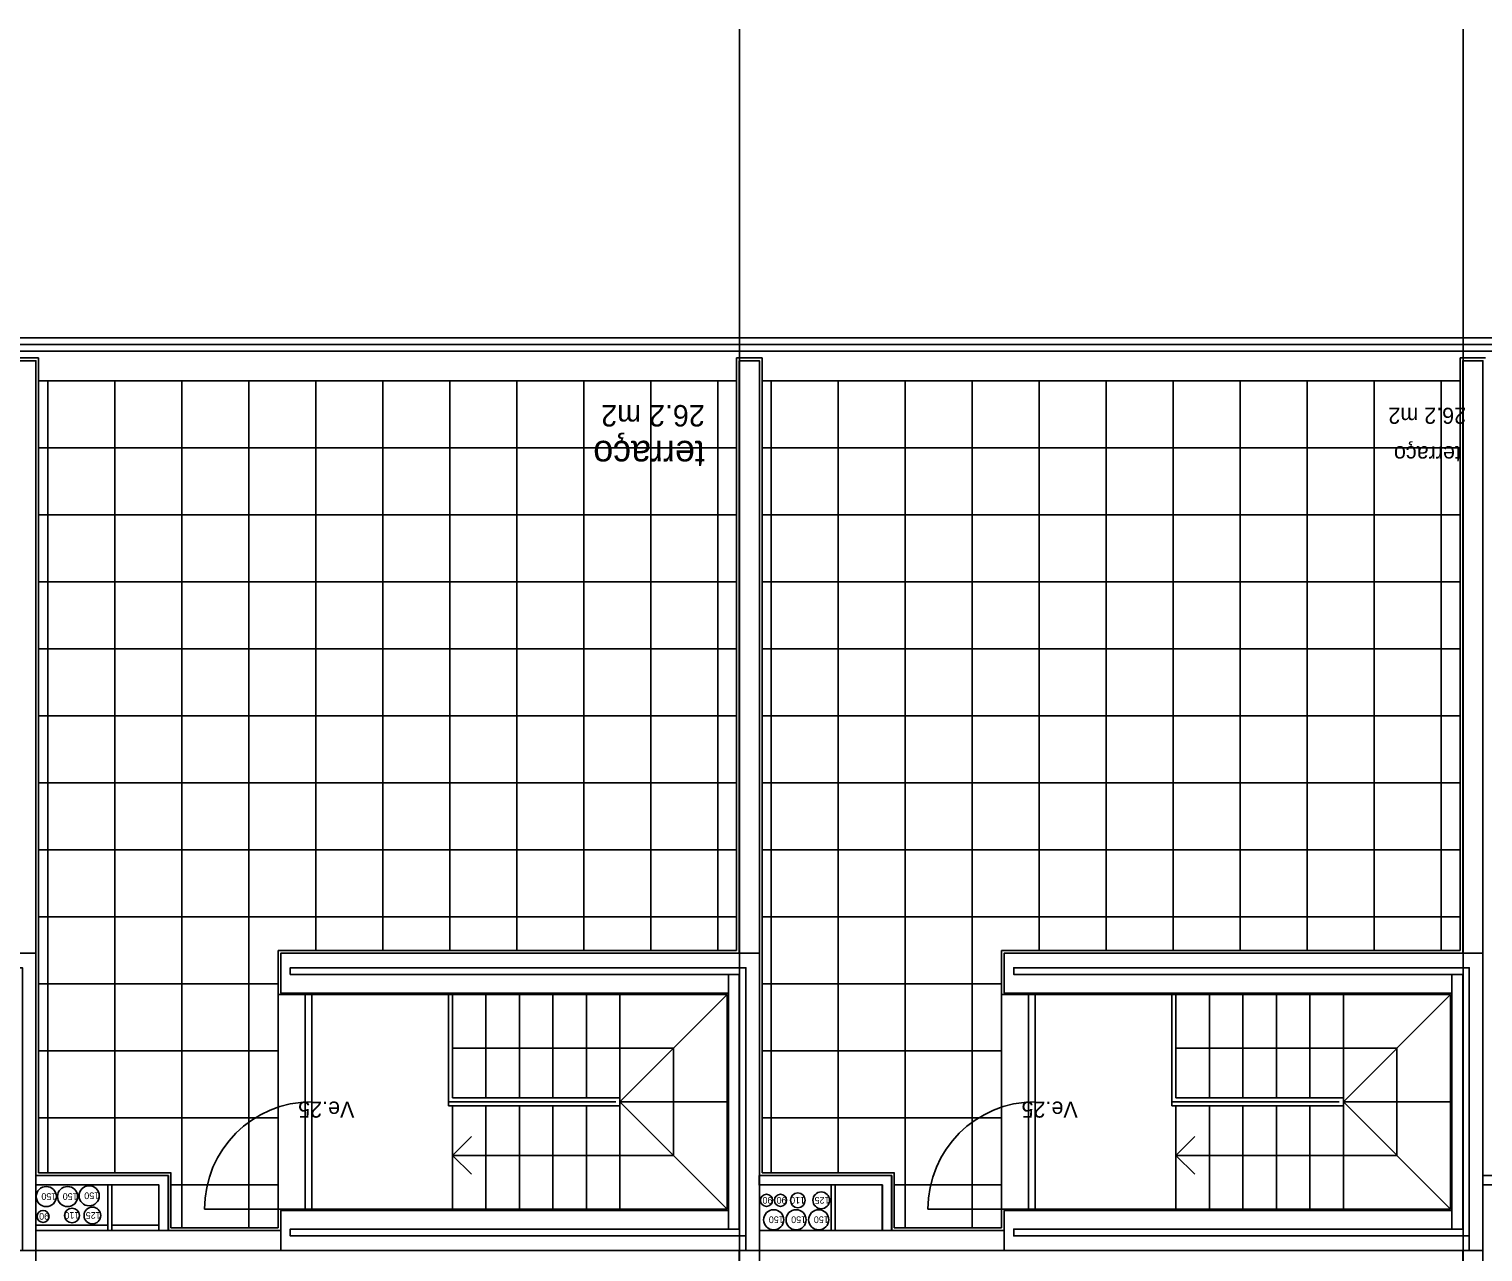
# Model space of a CAD drawing. Extents: x 1278 to 1356, y -253.7 to -224.
# Drawn here: x 1323.98 to 1334.83, y -238.74 to -229.62 of the extents above; entities that cross this region are included whole.
import ezdxf

# ---------------------------------------------------------------- set-up
doc = ezdxf.new("R2010")
doc.units = 0
for name, color, linetype in [('corte', 7, 'Continuous'), ('estereoctomias', 7, 'Continuous'), ('estrutura-eixos', 7, 'Continuous'), ('Level 1', 7, 'Continuous'), ('Level 13', 7, 'Continuous'), ('Level 2', 7, 'Continuous'), ('Level 21', 7, 'Continuous'), ('Level 40', 7, 'Continuous'), ('Level 41', 7, 'Continuous'), ('Level 60', 7, 'Continuous'), ('portas', 7, 'Continuous'), ('revestimentos', 7, 'Continuous'), ('vista', 7, 'Continuous')]:
    doc.layers.add(name, color=color, linetype=linetype)

msp = doc.modelspace()

# ---------------------------------------------------------------- linework, layer by layer
at = {"layer": 'corte'}
for p, q in [((1324.034, -232.094), (1323.884, -232.094)), ((1329.432, -232.094), (1329.282, -232.094)), ((1334.831, -232.094), (1334.681, -232.094)), ((1325.932, -236.624), (1329.332, -236.624)), ((1325.932, -236.674), (1325.932, -236.624)), ((1325.932, -236.674), (1329.282, -236.674)), ((1329.282, -236.674), (1329.282, -238.574)), ((1329.332, -236.624), (1329.332, -238.624)), ((1331.33, -236.624), (1334.73, -236.624)), ((1331.33, -236.674), (1331.33, -236.624)), ((1331.33, -236.674), (1334.681, -236.674)), ((1334.681, -236.674), (1334.681, -238.574)), ((1334.73, -236.624), (1334.73, -238.624)), ((1324.034, -238.174), (1325.022, -238.174)), ((1325.02, -238.174), (1325.02, -238.584)), ((1329.432, -238.174), (1330.42, -238.174)), ((1330.418, -238.174), (1330.418, -238.584)), ((1324.032, -238.244), (1324.952, -238.244)), ((1324.57, -238.584), (1324.57, -238.244)), ((1324.6, -238.584), (1324.6, -238.244)), ((1324.95, -238.244), (1324.95, -238.584)), ((1329.43, -238.244), (1330.35, -238.244)), ((1329.968, -238.584), (1329.968, -238.244)), ((1329.998, -238.584), (1329.998, -238.244)), ((1330.348, -238.244), (1330.348, -238.584)), ((1334.83, -238.244), (1335.75, -238.244)), ((1324.034, -238.584), (1325.862, -238.584)), ((1329.432, -238.584), (1331.26, -238.584)), ((1324.034, -238.734), (1329.432, -238.734)), ((1329.432, -238.734), (1334.831, -238.734))]:
    msp.add_line(p, q, dxfattribs=at)
at = {"layer": 'estereoctomias'}
for points in [[(1324.034, -236.514), (1323.884, -236.514), (1323.884, -232.094), (1324.034, -232.094)], [(1329.432, -236.514), (1329.282, -236.514), (1329.282, -232.094), (1329.432, -232.094)], [(1334.831, -236.514), (1334.681, -236.514), (1334.681, -232.094), (1334.831, -232.094)], [(1324.034, -236.514), (1324.034, -236.624), (1324.034, -238.734), (1323.933, -238.734), (1323.933, -236.624), (1320.533, -236.624), (1320.533, -236.674), (1323.884, -236.674), (1323.884, -236.814), (1323.884, -238.574), (1323.803, -238.574), (1323.803, -236.814), (1320.463, -236.814), (1320.463, -236.514)], [(1329.432, -236.514), (1329.432, -236.624), (1329.432, -238.734), (1329.332, -238.734), (1329.332, -236.624), (1325.932, -236.624), (1325.932, -236.674), (1329.282, -236.674), (1329.282, -236.814), (1329.282, -238.574), (1329.202, -238.574), (1329.202, -236.814), (1325.862, -236.814), (1325.862, -236.514)], [(1334.831, -236.514), (1334.831, -236.624), (1334.831, -238.734), (1334.73, -238.734), (1334.73, -236.624), (1331.33, -236.624), (1331.33, -236.674), (1334.681, -236.674), (1334.681, -236.814), (1334.681, -238.574), (1334.6, -238.574), (1334.6, -236.814), (1331.26, -236.814), (1331.26, -236.514)], [(1325.022, -238.584), (1324.952, -238.584), (1324.952, -238.244), (1324.032, -238.244), (1324.032, -238.174), (1325.022, -238.174)], [(1330.42, -238.584), (1330.35, -238.584), (1330.35, -238.244), (1329.43, -238.244), (1329.43, -238.174), (1330.42, -238.174)], [(1335.82, -238.584), (1335.75, -238.584), (1335.75, -238.244), (1334.83, -238.244), (1334.83, -238.174), (1335.82, -238.174)], [(1324.6, -238.584), (1324.57, -238.584), (1324.57, -238.244), (1324.6, -238.244)], [(1329.998, -238.584), (1329.968, -238.584), (1329.968, -238.244), (1329.998, -238.244)], [(1329.202, -238.434), (1329.202, -238.574), (1325.932, -238.574), (1325.932, -238.624), (1329.332, -238.624), (1329.332, -238.734), (1325.862, -238.734), (1324.034, -238.734), (1324.034, -238.584), (1325.862, -238.584), (1325.862, -238.434)], [(1334.6, -238.434), (1334.6, -238.574), (1331.33, -238.574), (1331.33, -238.624), (1334.73, -238.624), (1334.73, -238.734), (1331.26, -238.734), (1329.432, -238.734), (1329.432, -238.584), (1331.26, -238.584), (1331.26, -238.434)], [(1324.034, -240.114), (1323.884, -240.114), (1323.884, -238.734), (1324.034, -238.734)], [(1329.432, -240.114), (1329.282, -240.114), (1329.282, -238.734), (1329.432, -238.734)], [(1334.831, -240.114), (1334.681, -240.114), (1334.681, -238.734), (1334.831, -238.734)]]:
    msp.add_lwpolyline(points, close=True, dxfattribs=at)
at = {"layer": 'estrutura-eixos'}
for p, q in [((1329.284, -250.792), (1329.284, -229.62)), ((1334.684, -250.792), (1334.684, -229.62))]:
    msp.add_line(p, q, dxfattribs=at)
at = {"layer": 'Level 1'}
for p, q in [((1324.034, -232.094), (1324.034, -246.754)), ((1329.282, -232.094), (1329.282, -236.514)), ((1329.432, -232.094), (1329.432, -246.754)), ((1334.681, -232.094), (1334.681, -236.514)), ((1334.831, -232.094), (1334.831, -246.754)), ((1320.463, -236.514), (1324.034, -236.514)), ((1325.862, -236.514), (1329.432, -236.514)), ((1325.862, -236.514), (1325.862, -236.814)), ((1331.26, -236.514), (1334.831, -236.514)), ((1331.26, -236.514), (1331.26, -236.814)), ((1329.202, -236.674), (1329.202, -238.574)), ((1334.6, -236.674), (1334.6, -238.574)), ((1325.862, -236.814), (1329.202, -236.814)), ((1331.26, -236.814), (1334.6, -236.814)), ((1325.862, -238.434), (1329.202, -238.434)), ((1325.862, -238.434), (1325.862, -238.734)), ((1331.26, -238.434), (1334.6, -238.434)), ((1331.26, -238.434), (1331.26, -238.734)), ((1325.932, -238.574), (1329.282, -238.574)), ((1325.932, -238.574), (1325.932, -238.624)), ((1325.932, -238.624), (1329.332, -238.624)), ((1331.33, -238.574), (1334.681, -238.574)), ((1331.33, -238.574), (1331.33, -238.624)), ((1331.33, -238.624), (1334.73, -238.624)), ((1318.544, -238.734), (1324.034, -238.734)), ((1329.282, -240.114), (1329.282, -238.734)), ((1334.681, -240.114), (1334.681, -238.734))]:
    msp.add_line(p, q, dxfattribs=at)
at = {"layer": 'Level 13'}
for p, q in [((1326.042, -238.424), (1326.042, -236.824)), ((1326.092, -238.424), (1326.092, -236.824)), ((1331.44, -238.424), (1331.44, -236.824)), ((1331.49, -238.424), (1331.49, -236.824))]:
    msp.add_line(p, q, dxfattribs=at)
for centre in [(1326.092, -238.424), (1331.49, -238.424)]:
    msp.add_arc(centre, 0.8, 90, 180, dxfattribs=at)
at = {"layer": 'Level 2'}
for p, q in [((1318.543, -231.924), (1345.543, -231.924)), ((1345.543, -231.974), (1318.543, -231.974)), ((1345.543, -232.024), (1318.543, -232.024)), ((1324.054, -232.244), (1329.262, -232.244)), ((1329.452, -232.244), (1334.661, -232.244)), ((1325.842, -236.824), (1325.842, -238.424)), ((1327.112, -237.654), (1327.112, -236.824)), ((1327.142, -237.594), (1327.142, -236.824)), ((1327.142, -237.594), (1327.142, -236.824)), ((1327.392, -237.594), (1327.392, -236.824)), ((1327.642, -237.594), (1327.642, -236.824)), ((1327.892, -237.594), (1327.892, -236.824)), ((1328.142, -237.594), (1328.142, -236.824)), ((1328.392, -237.594), (1328.392, -236.824)), ((1328.392, -237.624), (1329.192, -236.824)), ((1331.24, -236.824), (1331.24, -238.424)), ((1332.51, -237.654), (1332.51, -236.824)), ((1332.54, -237.594), (1332.54, -236.824)), ((1332.54, -237.594), (1332.54, -236.824)), ((1332.79, -237.594), (1332.79, -236.824)), ((1333.04, -237.594), (1333.04, -236.824)), ((1333.29, -237.594), (1333.29, -236.824)), ((1333.54, -237.594), (1333.54, -236.824)), ((1333.79, -237.594), (1333.79, -236.824)), ((1333.79, -237.624), (1334.59, -236.824)), ((1327.142, -237.224), (1328.792, -237.224)), ((1328.792, -238.024), (1328.792, -237.224)), ((1332.54, -237.224), (1334.19, -237.224)), ((1334.19, -238.024), (1334.19, -237.224)), ((1328.36, -237.624), (1327.112, -237.624)), ((1328.392, -237.654), (1327.112, -237.654)), ((1328.392, -237.594), (1327.142, -237.594)), ((1327.142, -238.424), (1327.142, -237.654)), ((1327.392, -238.424), (1327.392, -237.654)), ((1327.642, -238.424), (1327.642, -237.654)), ((1327.892, -238.424), (1327.892, -237.654)), ((1328.142, -238.424), (1328.142, -237.654)), ((1328.392, -237.654), (1328.392, -237.594)), ((1329.192, -237.624), (1328.392, -237.624)), ((1328.392, -237.624), (1329.192, -238.424)), ((1328.392, -238.424), (1328.392, -237.654)), ((1333.759, -237.624), (1332.51, -237.624)), ((1333.79, -237.654), (1332.51, -237.654)), ((1333.79, -237.594), (1332.54, -237.594)), ((1332.54, -238.424), (1332.54, -237.654)), ((1332.79, -238.424), (1332.79, -237.654)), ((1333.04, -238.424), (1333.04, -237.654)), ((1333.29, -238.424), (1333.29, -237.654)), ((1333.54, -238.424), (1333.54, -237.654)), ((1333.79, -237.654), (1333.79, -237.594)), ((1334.59, -237.624), (1333.79, -237.624)), ((1333.79, -237.624), (1334.59, -238.424)), ((1333.79, -238.424), (1333.79, -237.654)), ((1327.283, -237.883), (1327.142, -238.024)), ((1332.682, -237.883), (1332.54, -238.024)), ((1328.792, -238.024), (1327.142, -238.024)), ((1327.283, -238.165), (1327.142, -238.024)), ((1334.19, -238.024), (1332.54, -238.024)), ((1332.682, -238.165), (1332.54, -238.024))]:
    msp.add_line(p, q, dxfattribs=at)
at = {"layer": 'Level 21'}
for p, q in [((1324.122, -238.154), (1324.122, -232.244)), ((1324.622, -238.154), (1324.622, -232.244)), ((1325.122, -238.564), (1325.122, -232.244)), ((1325.622, -238.564), (1325.622, -232.244)), ((1326.122, -236.494), (1326.122, -232.244)), ((1326.622, -236.494), (1326.622, -232.244)), ((1327.122, -236.494), (1327.122, -232.244)), ((1327.622, -236.494), (1327.622, -232.244)), ((1328.122, -236.494), (1328.122, -232.244)), ((1328.622, -236.494), (1328.622, -232.244)), ((1329.122, -236.494), (1329.122, -232.244)), ((1329.52, -238.154), (1329.52, -232.244)), ((1330.02, -238.154), (1330.02, -232.244)), ((1330.52, -238.564), (1330.52, -232.244)), ((1331.02, -238.564), (1331.02, -232.244)), ((1331.52, -236.494), (1331.52, -232.244)), ((1332.02, -236.494), (1332.02, -232.244)), ((1332.52, -236.494), (1332.52, -232.244)), ((1333.02, -236.494), (1333.02, -232.244)), ((1333.52, -236.494), (1333.52, -232.244)), ((1334.02, -236.494), (1334.02, -232.244)), ((1334.52, -236.494), (1334.52, -232.244)), ((1324.054, -232.744), (1329.262, -232.744)), ((1329.452, -232.744), (1334.661, -232.744)), ((1324.054, -233.244), (1329.262, -233.244)), ((1329.452, -233.244), (1334.661, -233.244)), ((1324.054, -233.744), (1329.262, -233.744)), ((1329.452, -233.744), (1334.661, -233.744)), ((1324.054, -234.244), (1329.262, -234.244)), ((1329.452, -234.244), (1334.661, -234.244)), ((1324.054, -234.744), (1329.262, -234.744)), ((1329.452, -234.744), (1334.661, -234.744)), ((1324.054, -235.244), (1329.262, -235.244)), ((1329.452, -235.244), (1334.661, -235.244)), ((1324.054, -235.744), (1329.262, -235.744)), ((1329.452, -235.744), (1334.661, -235.744)), ((1324.054, -236.244), (1329.262, -236.244)), ((1329.452, -236.244), (1334.661, -236.244)), ((1324.054, -236.744), (1325.842, -236.744)), ((1329.452, -236.744), (1331.24, -236.744)), ((1324.054, -237.244), (1325.842, -237.244)), ((1329.452, -237.244), (1331.24, -237.244)), ((1324.054, -237.744), (1325.842, -237.744)), ((1329.452, -237.744), (1331.24, -237.744)), ((1325.04, -238.244), (1325.842, -238.244)), ((1330.438, -238.244), (1331.24, -238.244))]:
    msp.add_line(p, q, dxfattribs=at)
at = {"layer": 'Level 41'}
for centre, radius in [((1324.111, -238.331), 0.075), ((1324.27, -238.331), 0.075), ((1324.431, -238.325), 0.075), ((1329.485, -238.359), 0.045), ((1329.59, -238.359), 0.045), ((1329.719, -238.359), 0.055), ((1329.894, -238.359), 0.0625), ((1324.087, -238.479), 0.045), ((1324.303, -238.472), 0.055), ((1324.455, -238.472), 0.0625), ((1329.539, -238.504), 0.075), ((1329.706, -238.504), 0.075), ((1329.875, -238.504), 0.075)]:
    msp.add_circle(centre, radius, dxfattribs=at)
at = {"layer": 'portas'}
for p, q in [((1326.042, -238.424), (1325.292, -238.424)), ((1331.44, -238.424), (1330.69, -238.424))]:
    msp.add_line(p, q, dxfattribs=at)
at = {"layer": 'revestimentos'}
for p, q in [((1324.054, -232.074), (1323.864, -232.074)), ((1324.054, -232.074), (1324.054, -238.154)), ((1329.452, -232.074), (1329.262, -232.074)), ((1329.262, -232.074), (1329.262, -236.494)), ((1329.452, -232.074), (1329.452, -238.154)), ((1334.661, -232.074), (1334.661, -236.494)), ((1334.851, -232.074), (1334.661, -232.074)), ((1325.842, -236.494), (1325.842, -236.824)), ((1325.842, -236.494), (1329.262, -236.494)), ((1331.24, -236.494), (1331.24, -236.824)), ((1331.24, -236.494), (1334.661, -236.494)), ((1325.842, -236.824), (1329.192, -236.824)), ((1329.192, -236.824), (1329.192, -238.424)), ((1331.24, -236.824), (1334.59, -236.824)), ((1334.59, -236.824), (1334.59, -238.424)), ((1324.054, -238.154), (1325.042, -238.154)), ((1325.04, -238.154), (1325.04, -238.564)), ((1329.452, -238.154), (1330.44, -238.154)), ((1330.438, -238.154), (1330.438, -238.564)), ((1325.842, -238.424), (1325.842, -238.564)), ((1325.842, -238.424), (1329.192, -238.424)), ((1331.24, -238.424), (1331.24, -238.564)), ((1331.24, -238.424), (1334.59, -238.424)), ((1325.04, -238.564), (1325.842, -238.564)), ((1330.438, -238.564), (1331.24, -238.564))]:
    msp.add_line(p, q, dxfattribs=at)
at = {"layer": 'vista'}
for p, q in [((1324.572, -238.544), (1324.032, -238.544)), ((1324.95, -238.544), (1324.6, -238.544))]:
    msp.add_line(p, q, dxfattribs=at)

# ---------------------------------------------------------------- texts
at = {"layer": 'Level 40'}
for p in [(1326.41, -237.622), (1331.808, -237.622)]:
    msp.add_text('Ve.25', height=0.12, rotation=180, dxfattribs=at).set_placement(p)
at = {"layer": 'Level 41'}
for s, p in [('150', (1324.186, -238.306)), ('150', (1324.345, -238.306)), ('150', (1324.506, -238.3)), ('90', (1329.53, -238.334)), ('90', (1329.635, -238.334)), ('110', (1329.774, -238.334)), ('125', (1329.956, -238.334)), ('90', (1324.132, -238.454)), ('110', (1324.358, -238.447)), ('125', (1324.517, -238.447)), ('150', (1329.614, -238.479)), ('150', (1329.781, -238.479)), ('150', (1329.95, -238.479))]:
    msp.add_text(s, height=0.05, rotation=180, dxfattribs=at).set_placement(p)
at = {"layer": 'Level 60'}
for s, height, p in [('26.2 m2', 0.16, (1329.025, -232.425)), ('26.2 m2', 0.12, (1334.706, -232.445)), ('terraço', 0.2, (1329.025, -232.692)), ('terraço', 0.12, (1334.667, -232.732))]:
    msp.add_text(s, height=height, rotation=180, dxfattribs=at).set_placement(p)

doc.saveas('drawing.dxf')
